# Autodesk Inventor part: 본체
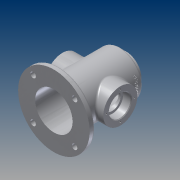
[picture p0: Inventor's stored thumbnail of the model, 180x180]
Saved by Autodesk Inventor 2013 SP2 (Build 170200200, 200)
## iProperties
Created: 2014-12
Part Number: 본체
Material: 알루미늄 6061
Document SubType Name: Modeling
Designer: CADB302
Density: 2.71 g/cm^3
Mass: 477.581 g
Surface Area: 612.215 cm^2
Volume: 176.229 cm^3
Author: CADB302
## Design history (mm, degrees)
sketch "스케치1"
  geometry: L1 (32.5, -55)-(-32.5, -55); L2 (-32.5, -55)-(-32.5, 43); L3 (-32.5, 43)-(32.5, 43); L4 (32.5, 43)-(32.5, -55); 2 further points
  constraints: 8 end point, 2 parallel, 1 horizontal, 1 midpoint, 1 perpendicular, 1 vertical alignment
  dimensions: "d0" = 65 distance of L2.end L3.end; "d2" = 98 distance between parallel lines of L1 L3; "d3" = 55 distance from line of L1 point (0, 0)
extrude "돌출1" new body sketch "스케치1" stored distance "d4" = 65; taper "d5" = 0 deg
fillet "모깎기1" dims "d6" = 32.5
fillet "모깎기2" dims "d8" = 3
feature "쉘1" dims "d9" = 5
sketch "스케치3"
  geometry: C1 r 52.5 at (0, 0); C2 r 27.5 at (0, 0) reference; 1 further point
  constraints: 1 centre point, 1 coincident
  dimensions: "d10" = 105 diameter of C1
extrude "돌출2" join sketch "스케치3" distance "d12" = 8; taper "d13" = 0 deg
node "작업 평면1"
sketch "스케치4"
  geometry: C1 r 25 at (0, 0); 1 further point
  constraints: 1 centre point, 1 coincident
  dimensions: "d15" = 50 diameter of C1
extrude "돌출3" join sketch "스케치4" stored distance "d16" = 8; taper "d17" = 0 deg
hole "구멍1" diameter "d20" = 25; stored, may be unused: countersink angle "d24" = 90 deg, drill point angle "d26" = 0 deg; dims "d18" = 10, "d19" = 10, "d21" = 6, "d22" = 32, "d23" = 12, "d25" = 8
sketch "스케치5"
  geometry: 2 further points
  constraints: 1 vertical alignment
  dimensions: "d27" = 20.5 distance of point (0, 0) point (0, 20.5)
hole "구멍2" sketch "스케치5" at (0, 20.5) diameter "d28" = 2.459; stored, may be unused: countersink angle "d32" = 90 deg, drill point angle "d34" = 118 deg; dims "d29" = 6, "d30" = 32, "d31" = 12, "d33" = 8
fillet "모깎기3" dims "d38" = 3
chamfer "모따기1" distance "d39" = 1; stored, may be unused: second distance "d40" = 2, angle "d41" = 45 deg
sketch "스케치6"
  geometry: C1 r 22.5 at (0, 0); 1 further point
  constraints: 1 centre point, 1 coincident
  dimensions: "d42" = 45 diameter of C1
extrude "돌출4" join sketch "스케치6" distance "d43" = 8; taper "d44" = 0 deg
hole "구멍3" diameter "d47" = 27; stored, may be unused: countersink angle "d51" = 90 deg, drill point angle "d53" = 0 deg; dims "d45" = 10, "d46" = 10, "d48" = 6, "d49" = 32, "d50" = 12, "d52" = 8
sketch "스케치8"
  geometry: 2 further points
  constraints: 1 vertical alignment
  dimensions: "d54" = 17.5 distance of point (0, 0) point (0, 17.5)
hole "구멍4" sketch "스케치8" at (0, 17.5) diameter "d55" = 2.459; stored, may be unused: countersink angle "d59" = 90 deg, drill point angle "d61" = 118 deg; dims "d56" = 6, "d57" = 32, "d58" = 12, "d60" = 8
fillet "모깎기4" dims "d65" = 0.3, "d66" = 3
chamfer "모따기2" distance "d67" = 1; stored, may be unused: second distance "d68" = 2, angle "d69" = 45 deg
sketch "스케치9"
  geometry: L1 (30.406, 30.406)-(0, 0); L2 (0, 0)-(0, 58.137)
  constraints: 4 end point, 1 vertical
  dimensions: "d70" = 43 distance of L1.start L1.end; "d71" = 45 deg angle of L2 L1
hole "구멍5" sketch "스케치9" at (30.406, 30.406) diameter "d72" = 8; stored, may be unused: countersink angle "d76" = 90 deg, drill point angle "d78" = 0 deg; dims "d73" = 6, "d74" = 32, "d75" = 12, "d77" = 8
node "작업 평면2"
sketch "스케치10"
  geometry: L1 (43, 29.5)-(43, -29.5) reference; 2 further points
  constraints: 1 horizontal alignment, 1 other
  dimensions: "d84" = 9 distance from line of point (34, 0) L1
feature "엠보싱1" sketch "스케치10" dims "d0" = 65, "d2" = 98, "d3" = 55, "d85" = 1, "d86" = 0
fillet "모깎기5" dims "d87" = 3
node "솔리드1"
pattern_circular "원형 패턴1" dims angle "d36" = 360 deg
mirror "대칭1"
pattern_circular "원형 패턴2" dims angle "d63" = 360 deg
pattern_circular "원형 패턴3" dims angle "d80" = 360 deg
other parameters: "d14" = 42.5, "d82" = 32.5
